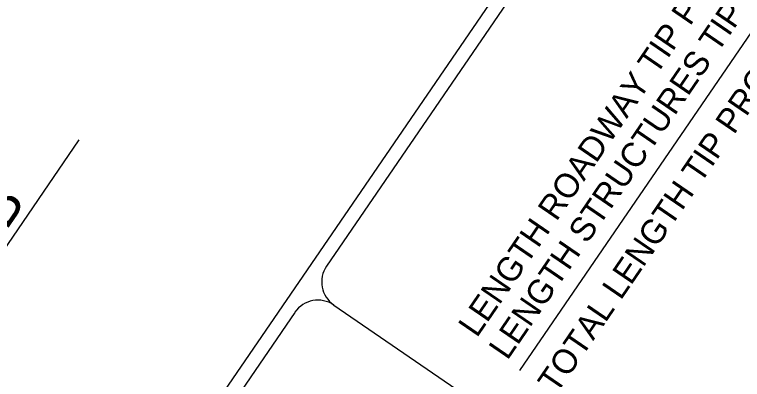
# Model space of a CAD drawing. Extents: x 2312641 to 2338852, y 590461 to 618614.
# Drawn here: x 2326066 to 2329705, y 598163 to 599985 of the extents above; entities that cross this region are included whole.
import ezdxf

# ---------------------------------------------------------------- set-up
doc = ezdxf.new("R2010")
doc.units = 0
for name, color, linetype in [('Default', 7, 'Continuous'), ('Exist Property Iron Pin Cogo Number', 7, 'Continuous'), ('Exist Structure Minor Head and End Wall Text', 7, 'Continuous'), ('Exist Structure Minor Pipes RCP 15 Inch Text', 7, 'Continuous')]:
    doc.layers.add(name, color=color, linetype=linetype)

msp = doc.modelspace()

# ---------------------------------------------------------------- linework, layer by layer
at = {"layer": 'Default'}
msp.add_line((2328591.3, 598207.7), (2331505.2, 602459.5), dxfattribs=at)
at = {"layer": 'Exist Property Iron Pin Cogo Number'}
for p, q in [((2324877.7, 594842), (2336116.1, 611240.6)), ((2327626.5, 598728.8), (2330633.9, 603117.1)), ((2327662.6, 598534.2), (2329510.4, 597267.9)), ((2326320.6, 596823.3), (2327468, 598497.9))]:
    msp.add_line(p, q, dxfattribs=at)
for centre, start, end in [((2327741.3, 598650.1), 145.5761, 235.5761), ((2327583, 598419.2), 55.5761, 145.5761)]:
    msp.add_arc(centre, 140, start, end, dxfattribs=at)
at = {"layer": 'Exist Structure Minor Pipes RCP 15 Inch Text'}
msp.add_line((2326387.6, 599359.5), (2323924, 595764.7), dxfattribs=at)

# ---------------------------------------------------------------- texts
at = {"layer": 'Default'}
for s, p in [('LENGTH STRUCTURES TIP PROJECT U-3609B =', (2328529.7, 598255)), ('LENGTH ROADWAY TIP PROJECT U-3609B =', (2328376.9, 598367.6)), ('TOTAL LENGTH TIP PROJECT U-3609B =', (2328775.1, 598085.6))]:
    msp.add_text(s, height=121.5, rotation=55.6077, dxfattribs=at).set_placement(p)
at = {"layer": 'Exist Structure Minor Head and End Wall Text'}
for s, p in [('A PORTION OF THIS PROJECT IS WITHIN THE MUNICIPAL BOUNDARIES OF THE CITY OF GOLDSBORO.', (2327688.5, 592968.5)), ('CLEARING ON THIS PROJECT SHALL BE PERFORMED TO THE LIMITS ESTABLISHED BY METHOD III.', (2327557.7, 593058.1))]:
    msp.add_text(s, height=122.5, rotation=55.5761, dxfattribs=at).set_placement(p)
at = {"layer": 'Exist Structure Minor Pipes RCP 15 Inch Text'}
msp.add_text('BEGIN TIP PROJECT U-3609B', height=200, rotation=55.5761, dxfattribs=at).set_placement((2323990.8, 595936.5))

doc.saveas('drawing.dxf')
